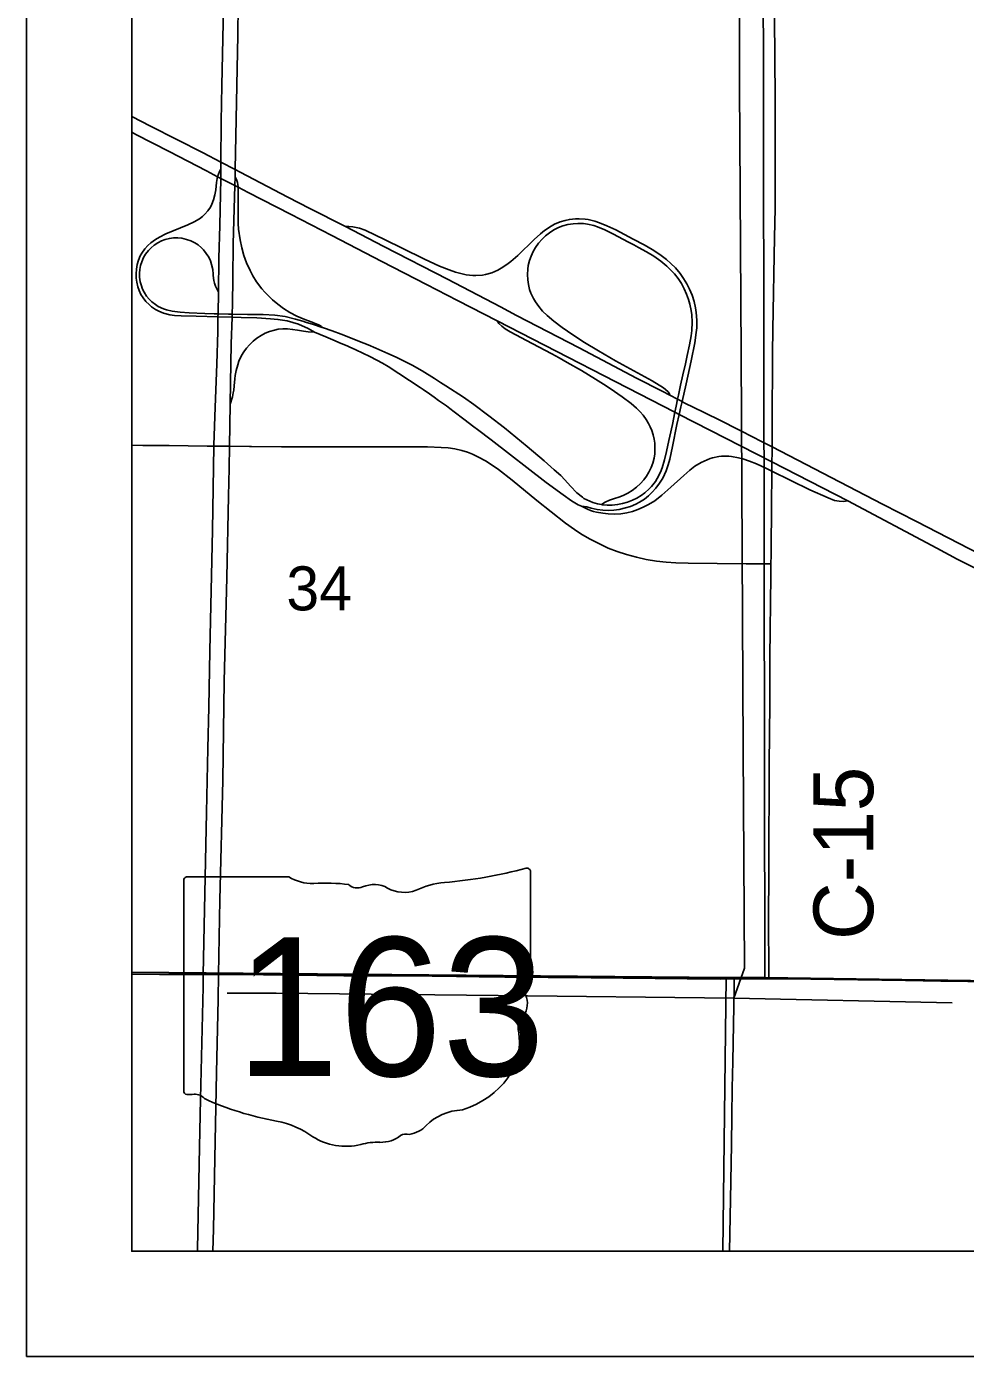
# Model space of a CAD drawing. Extents: x 0 to 34, y 0 to 22.
# Drawn here: x 2 to 2.893, y 14 to 15.265 of the extents above; entities that cross this region are included whole.
import ezdxf

# ---------------------------------------------------------------- set-up
doc = ezdxf.new("R2010")
doc.units = 0
for name, color, linetype in [('Default', 7, 'Continuous'), ('GM_X_County_Road', 7, 'Continuous'), ('GM_X_County_Road_Text', 7, 'Continuous'), ('GM_X_Interchange_Ramps', 7, 'Continuous'), ('GM_X_Interstate_Route', 7, 'Continuous'), ('GM_X_Minor_River', 7, 'Continuous'), ('GM_X_Section', 7, 'Continuous'), ('GM_X_Section_Text', 7, 'Continuous'), ('GM_X_State_Location', 7, 'Continuous'), ('GM_X_State_Route', 7, 'Continuous'), ('GM_X_State_Shield', 7, 'Continuous'), ('GM_X_Township_Road', 7, 'Continuous'), ('SH_Data', 7, 'Continuous')]:
    doc.layers.add(name, color=color, linetype=linetype)

msp = doc.modelspace()

# ---------------------------------------------------------------- linework, layer by layer
at = {"layer": 'Default'}
for points in [[(2.1, 15.3673), (2.1, 14.3654), (2.6651, 14.3602), (2.7019, 14.3602), (2.7001, 15.3638)], [(2.1, 14.3654), (2.1, 14.1), (2.662, 14.1), (2.6651, 14.3602)], [(2.662, 14.1), (3.676, 14.1), (3.6799, 14.3459), (2.7019, 14.3602), (2.6651, 14.3602)]]:
    msp.add_lwpolyline(points, close=True, dxfattribs=at)
at = {"layer": 'GM_X_County_Road'}
for points in [[(2.7076, 14.7538), (2.7078, 14.762), (2.7081, 14.8136), (2.7085, 14.8357), (2.7085, 14.8418), (2.7086, 14.8505), (2.7087, 14.8596), (2.7087, 14.865), (2.7088, 14.8824), (2.7089, 14.9074), (2.7092, 14.9316), (2.7091, 14.954), (2.7095, 14.9764), (2.7111, 15.064), (2.7116, 15.0914), (2.7115, 15.1045), (2.7116, 15.1337), (2.7116, 15.1902), (2.7112, 15.2413), (2.7105, 15.319), (2.7106, 15.3539), (2.7102, 15.3684)], [(2.7055, 14.359), (2.7055, 14.369), (2.7054, 14.4113), (2.7056, 14.4648), (2.7061, 14.563), (2.7065, 14.6208), (2.7067, 14.665), (2.7074, 14.7421), (2.7076, 14.7538)], [(2.6683, 14.1), (2.6692, 14.1493), (2.6702, 14.2016), (2.6705, 14.2283), (2.6709, 14.255), (2.6714, 14.2805), (2.6726, 14.3508), (2.6728, 14.3589)], [(2.6728, 14.3589), (2.6841, 14.359), (2.7055, 14.359)]]:
    msp.add_lwpolyline(points, dxfattribs=at)
at = {"layer": 'GM_X_Interchange_Ramps'}
for points in [[(2.1848, 15.1291), (2.1835, 15.1267), (2.1824, 15.1243), (2.1816, 15.1217), (2.1811, 15.1201), (2.1805, 15.1162), (2.1799, 15.1094), (2.1791, 15.1045), (2.1778, 15.0997), (2.1762, 15.0956), (2.1748, 15.0928), (2.1724, 15.0892), (2.1695, 15.086), (2.1672, 15.0839), (2.1643, 15.0817), (2.1594, 15.0788), (2.1532, 15.076), (2.1325, 15.0674), (2.1263, 15.0644), (2.1225, 15.0622), (2.118, 15.059), (2.1152, 15.0565), (2.1123, 15.0533), (2.1095, 15.0491), (2.1081, 15.0464), (2.1064, 15.0424), (2.1052, 15.0382), (2.1044, 15.0339), (2.1041, 15.0295), (2.1042, 15.0252), (2.1047, 15.0215), (2.1056, 15.0172), (2.1069, 15.0137), (2.1087, 15.0098), (2.1107, 15.0066), (2.1133, 15.0031), (2.1164, 15.0001), (2.1188, 14.9981), (2.1224, 14.9956), (2.1257, 14.9939), (2.1303, 14.992), (2.1363, 14.9905), (2.1406, 14.9899), (2.1468, 14.9894), (2.1611, 14.989), (2.1819, 14.9885), (2.1954, 14.9882), (2.2041, 14.988), (2.219, 14.9875), (2.232, 14.9867), (2.239, 14.9861), (2.2476, 14.9846), (2.2584, 14.9815), (2.2677, 14.9775), (2.2738, 14.9741)], [(2.281, 14.9784), (2.2803, 14.9793), (2.2795, 14.9799), (2.2785, 14.9805), (2.2743, 14.9823), (2.2714, 14.9834), (2.2644, 14.9859), (2.257, 14.989), (2.2504, 14.9926), (2.2441, 14.9965), (2.2387, 15.0007), (2.2339, 15.0047), (2.2264, 15.0121), (2.2235, 15.0153), (2.2187, 15.0218), (2.2151, 15.0276), (2.2124, 15.0325), (2.2091, 15.0398), (2.2066, 15.0468), (2.2046, 15.054), (2.2029, 15.0619), (2.2016, 15.0718), (2.2011, 15.0773), (2.2011, 15.1074), (2.2011, 15.1117), (2.201, 15.1126), (2.2004, 15.1164), (2.1996, 15.1191), (2.1983, 15.1218)], [(2.5275, 14.8085), (2.5326, 14.808), (2.5368, 14.8066), (2.5423, 14.8054), (2.5479, 14.8047), (2.5528, 14.8045), (2.5584, 14.8048), (2.5633, 14.8054), (2.5694, 14.8068), (2.5742, 14.8083), (2.5793, 14.8105), (2.5826, 14.8123), (2.5873, 14.8153), (2.5912, 14.8184), (2.5948, 14.8218), (2.5981, 14.8255), (2.6018, 14.8305), (2.6048, 14.8352), (2.6079, 14.842), (2.6099, 14.8478), (2.6114, 14.8532), (2.614, 14.8653), (2.6183, 14.8861), (2.6204, 14.8958), (2.622, 14.9031), (2.6231, 14.908), (2.6269, 14.9249), (2.6317, 14.9467), (2.6352, 14.9638), (2.6367, 14.9736), (2.6371, 14.978), (2.6373, 14.9854), (2.6367, 14.9928), (2.636, 14.9971), (2.6346, 15.0031), (2.6327, 15.009), (2.6303, 15.0148), (2.6278, 15.0198), (2.6246, 15.0251), (2.6214, 15.0297), (2.617, 15.035), (2.6126, 15.0393), (2.6084, 15.043), (2.602, 15.0479), (2.5946, 15.0526), (2.5871, 15.0569), (2.5767, 15.0625), (2.5684, 15.0668), (2.5601, 15.0711), (2.5517, 15.0752), (2.5448, 15.078), (2.5401, 15.0796), (2.534, 15.081), (2.531, 15.0814), (2.5254, 15.0818), (2.5217, 15.0817), (2.5161, 15.0811), (2.5119, 15.0802), (2.5071, 15.0788), (2.502, 15.0765), (2.4987, 15.0748), (2.4925, 15.0707), (2.4886, 15.0676), (2.4826, 15.0622), (2.467, 15.047), (2.4604, 15.0412), (2.4565, 15.0382), (2.4513, 15.0347), (2.448, 15.033), (2.4424, 15.0305), (2.4364, 15.0289), (2.4333, 15.0283), (2.4272, 15.0279), (2.4241, 15.0279), (2.4179, 15.0286), (2.4142, 15.0293), (2.4076, 15.0311), (2.4017, 15.0331), (2.3925, 15.0368), (2.3783, 15.0433), (2.3572, 15.0537), (2.341, 15.0616), (2.3219, 15.0709), (2.3164, 15.0728), (2.3102, 15.0741), (2.3024, 15.0746)], [(2.6114, 14.9139), (2.6108, 14.9159), (2.6096, 14.9174), (2.6055, 14.9209), (2.5947, 14.9278), (2.5598, 14.9468), (2.5436, 14.9561), (2.5303, 14.9642), (2.5194, 14.9713), (2.5092, 14.9784), (2.5012, 14.9844), (2.495, 14.9897), (2.4906, 14.994), (2.4869, 14.9982), (2.4837, 15.0028), (2.4818, 15.006), (2.4794, 15.0111), (2.4782, 15.0146), (2.477, 15.0194), (2.4764, 15.0237), (2.4761, 15.0287), (2.4764, 15.0337), (2.4769, 15.0374), (2.4781, 15.0422), (2.4796, 15.0463), (2.4817, 15.0508), (2.4839, 15.0546), (2.4867, 15.0587), (2.49, 15.0624), (2.4932, 15.0654), (2.4971, 15.0684), (2.5013, 15.0711), (2.5058, 15.0734), (2.5098, 15.0749), (2.5146, 15.0763), (2.5195, 15.077), (2.5239, 15.0774), (2.5294, 15.0772), (2.5332, 15.0767), (2.5392, 15.0753), (2.5427, 15.0742), (2.5497, 15.0713), (2.558, 15.0672), (2.5717, 15.0598), (2.5773, 15.057), (2.5816, 15.0545), (2.5893, 15.0504), (2.5962, 15.0462), (2.6028, 15.0415), (2.6086, 15.0368), (2.6113, 15.0343), (2.616, 15.0293), (2.6194, 15.0249), (2.6225, 15.0202), (2.6252, 15.0153), (2.6275, 15.0102), (2.6293, 15.0049), (2.6305, 15.0007), (2.6317, 14.9946), (2.6323, 14.9903), (2.6327, 14.9835), (2.6323, 14.9755), (2.6317, 14.9705), (2.6303, 14.9619), (2.628, 14.9516), (2.6263, 14.9437), (2.624, 14.9334), (2.6218, 14.9237), (2.6197, 14.914), (2.6189, 14.9101), (2.6176, 14.9036), (2.6164, 14.8979), (2.6139, 14.886), (2.6116, 14.875), (2.6106, 14.8708), (2.6085, 14.8604), (2.6066, 14.8526), (2.6042, 14.8448), (2.6027, 14.8408), (2.5995, 14.8347), (2.5979, 14.8321), (2.594, 14.8272), (2.5919, 14.825), (2.5877, 14.8213), (2.5842, 14.8187), (2.58, 14.8161), (2.5761, 14.8142), (2.5714, 14.8124), (2.5666, 14.811), (2.5618, 14.81), (2.5568, 14.8095), (2.5518, 14.8095), (2.5475, 14.8099), (2.5466, 14.8101)], [(2.281, 14.9784), (2.2728, 14.9812), (2.2651, 14.9835), (2.2627, 14.9843), (2.2556, 14.9864), (2.2459, 14.9887), (2.236, 14.99), (2.2249, 14.9906), (2.2099, 14.9909), (2.1954, 14.991), (2.1919, 14.991), (2.182, 14.9913), (2.1782, 14.9914), (2.1695, 14.9916), (2.1546, 14.9923), (2.1459, 14.993), (2.1385, 14.9939), (2.1331, 14.9951), (2.1301, 14.9961), (2.1251, 14.9985), (2.1225, 15.0001), (2.119, 15.0028), (2.1164, 15.0054), (2.114, 15.0083), (2.1117, 15.0119), (2.1103, 15.0147), (2.1088, 15.0188), (2.108, 15.0218), (2.1074, 15.0261), (2.1074, 15.0299), (2.1077, 15.0336), (2.1084, 15.0372), (2.1094, 15.0408), (2.1112, 15.0448), (2.1131, 15.048), (2.1158, 15.0515), (2.1183, 15.0542), (2.1212, 15.0566), (2.1248, 15.059), (2.1281, 15.0607), (2.1316, 15.0621), (2.1358, 15.0631), (2.1395, 15.0635), (2.1439, 15.0636), (2.1476, 15.0632), (2.1519, 15.0622), (2.156, 15.0609), (2.1599, 15.0589), (2.163, 15.0569), (2.1664, 15.0541), (2.1681, 15.0523), (2.1708, 15.0489), (2.1731, 15.0452), (2.1747, 15.0419), (2.1758, 15.0383), (2.1769, 15.0334), (2.1774, 15.0291), (2.1775, 15.0279), (2.1781, 15.0231), (2.1786, 15.0205), (2.1796, 15.0176), (2.1823, 15.0119)], [(2.4473, 14.9847), (2.449, 14.9823), (2.4518, 14.9795), (2.4551, 14.9771), (2.4598, 14.9744), (2.4806, 14.9632), (2.4993, 14.9533), (2.5064, 14.9495), (2.514, 14.9452), (2.5274, 14.9374), (2.5407, 14.9293), (2.5486, 14.9244), (2.5548, 14.9203), (2.5661, 14.9126), (2.5746, 14.9062), (2.5797, 14.9018), (2.5832, 14.8982), (2.5861, 14.8949), (2.589, 14.8909), (2.5913, 14.8872), (2.5929, 14.8839), (2.5943, 14.8804), (2.5957, 14.8763), (2.5966, 14.8721), (2.5972, 14.8684), (2.5974, 14.8634), (2.5972, 14.8584), (2.5965, 14.8541), (2.5953, 14.8493), (2.5938, 14.8452), (2.5917, 14.8407), (2.5894, 14.837), (2.5868, 14.8336), (2.5835, 14.8299), (2.5798, 14.8265), (2.5758, 14.8235), (2.5716, 14.8208), (2.5672, 14.8186), (2.5631, 14.8171), (2.5589, 14.8159), (2.554, 14.8142), (2.55, 14.8123), (2.5466, 14.8101)], [(2.1936, 14.9054), (2.1957, 14.9124), (2.1965, 14.9163), (2.197, 14.9188), (2.1972, 14.9228), (2.1979, 14.9296), (2.1984, 14.9327), (2.1993, 14.9376), (2.2007, 14.943), (2.2019, 14.9465), (2.2042, 14.9516), (2.2065, 14.9552), (2.209, 14.9588), (2.2119, 14.962), (2.2155, 14.9654), (2.2189, 14.9682), (2.223, 14.9709), (2.2269, 14.9729), (2.2309, 14.9745), (2.2356, 14.976), (2.2393, 14.9767), (2.2436, 14.9772), (2.2479, 14.9771), (2.2529, 14.9765), (2.2576, 14.9757), (2.2631, 14.975), (2.2678, 14.9744), (2.2738, 14.9741)], [(2.2738, 14.9741), (2.2845, 14.9695), (2.2911, 14.9667), (2.2992, 14.9633), (2.3049, 14.9608), (2.3066, 14.96), (2.3129, 14.9573), (2.3196, 14.9541), (2.3263, 14.9508), (2.3329, 14.9474), (2.3383, 14.9445), (2.3436, 14.9413), (2.3742, 14.9213), (2.3769, 14.9195), (2.3829, 14.9153), (2.3876, 14.912), (2.3917, 14.9091), (2.3991, 14.9038), (2.4023, 14.9014), (2.4064, 14.8983), (2.4157, 14.8913), (2.4253, 14.8838), (2.4288, 14.8813), (2.4416, 14.8716), (2.494, 14.831), (2.51, 14.8192), (2.5181, 14.8137), (2.5245, 14.8099), (2.5275, 14.8085)], [(2.5466, 14.8101), (2.5426, 14.8108), (2.5384, 14.812), (2.5355, 14.8131), (2.5299, 14.8158), (2.5284, 14.8169), (2.5232, 14.8213), (2.5172, 14.8276), (2.5118, 14.8336), (2.5079, 14.8376), (2.5016, 14.8431), (2.492, 14.8516), (2.4758, 14.8652), (2.4543, 14.883), (2.4395, 14.8944), (2.4251, 14.9053), (2.4154, 14.912), (2.3987, 14.9228), (2.3935, 14.9262), (2.3878, 14.9299), (2.3761, 14.9371), (2.3664, 14.9426), (2.3558, 14.9479), (2.3514, 14.9501), (2.3434, 14.9537), (2.3321, 14.9588), (2.3247, 14.962), (2.3166, 14.9652), (2.3032, 14.9703), (2.2992, 14.9719), (2.2904, 14.9751), (2.2822, 14.978), (2.281, 14.9784)], [(2.5275, 14.8085), (2.5294, 14.8075), (2.5331, 14.8056), (2.5362, 14.8043), (2.5388, 14.8035), (2.5417, 14.8029), (2.5479, 14.8018), (2.5529, 14.8012), (2.5593, 14.8008), (2.5649, 14.8013), (2.5705, 14.8022), (2.5759, 14.8035), (2.5812, 14.8053), (2.5863, 14.8075), (2.5913, 14.8101), (2.5971, 14.8137), (2.604, 14.819), (2.6124, 14.8264), (2.6248, 14.8378), (2.6305, 14.8426), (2.6354, 14.8464), (2.6413, 14.85), (2.644, 14.8514), (2.6498, 14.8537), (2.6521, 14.8544), (2.6582, 14.8556), (2.6607, 14.8559), (2.6675, 14.8559), (2.67, 14.8557), (2.6767, 14.8545), (2.6809, 14.8534), (2.6874, 14.8513), (2.6938, 14.8487), (2.704, 14.8441), (2.7085, 14.8418), (2.7447, 14.8241), (2.7621, 14.8164), (2.7682, 14.8139), (2.7724, 14.8132), (2.7763, 14.8129), (2.7808, 14.8135)]]:
    msp.add_lwpolyline(points, dxfattribs=at)
at = {"layer": 'GM_X_Interstate_Route'}
for points in [[(2.1, 20.9), (2.1, 14.3639), (2.1262, 14.3636), (2.1461, 14.3637), (2.161, 14.3637), (2.1678, 14.3636), (2.179, 14.3636), (2.1822, 14.3636), (2.1952, 14.3635), (2.225, 14.3635), (2.2499, 14.3631), (2.3015, 14.3626), (2.3854, 14.362), (2.4084, 14.3617), (2.4301, 14.3614), (2.4544, 14.3611), (2.5365, 14.3604), (2.6279, 14.3594), (2.6596, 14.3593), (2.6725, 14.3594), (2.6838, 14.3596), (2.7053, 14.3596), (2.723, 14.3595), (2.7901, 14.3585), (2.8355, 14.3579), (2.8691, 14.3573), (2.8946, 14.3569)], [(2.1848, 15.1291), (2.1848, 15.1356), (2.1851, 15.1744), (2.1857, 15.2086), (2.1874, 15.2981)], [(2.1983, 15.1218), (2.1984, 15.1285), (2.2007, 15.2563), (2.2012, 15.285)], [(2.1, 15.179), (2.1179, 15.1697), (2.1677, 15.1444), (2.1848, 15.1356), (2.1984, 15.1285), (2.2031, 15.1261), (2.2482, 15.1024), (2.2692, 15.0916), (2.3024, 15.0746), (2.3395, 15.0555), (2.4002, 15.0242), (2.4504, 14.9981), (2.4658, 14.9899), (2.5253, 14.9589), (2.5583, 14.9416), (2.5798, 14.9303), (2.6041, 14.9177), (2.6114, 14.9139), (2.6189, 14.9101), (2.6231, 14.908), (2.6251, 14.9069), (2.644, 14.8974), (2.6602, 14.8896), (2.6757, 14.8817), (2.6934, 14.8727), (2.6956, 14.8715), (2.7051, 14.8669), (2.7087, 14.865), (2.757, 14.8399), (2.8138, 14.8105), (2.8459, 14.794), (2.9769, 14.7265)], [(2.1, 15.1641), (2.104, 15.162), (2.1354, 15.1456), (2.171, 15.1273)], [(2.171, 15.1273), (2.1816, 15.1217), (2.1846, 15.1202), (2.198, 15.1133), (2.2011, 15.1117), (2.2105, 15.1068), (2.2509, 15.0861), (2.2902, 15.0659), (2.3376, 15.0412), (2.3802, 15.0192)], [(2.3802, 15.0192), (2.4095, 15.0041), (2.4473, 14.9847)], [(2.4473, 14.9847), (2.6164, 14.8979), (2.6204, 14.8958), (2.7086, 14.8505), (2.7808, 14.8135)], [(2.7808, 14.8135), (2.8655, 14.7685), (2.8848, 14.7582), (2.9264, 14.7371), (3.0022, 14.6983), (3.1397, 14.6271), (3.2203, 14.5854), (3.3213, 14.533), (3.3689, 14.5086), (3.4054, 14.4898), (3.4722, 14.4553), (3.533, 14.4239), (3.5854, 14.3967), (3.6138, 14.3818)], [(2.8946, 14.3569), (2.8691, 14.3573), (2.8355, 14.3579), (2.7901, 14.3585), (2.723, 14.3595), (2.7053, 14.3596), (2.6838, 14.3596), (2.6725, 14.3594), (2.6596, 14.3593), (2.6279, 14.3594), (2.5365, 14.3604), (2.4544, 14.3611), (2.4301, 14.3614), (2.4084, 14.3617), (2.3854, 14.362), (2.3015, 14.3626), (2.2499, 14.3631), (2.225, 14.3635), (2.1952, 14.3635), (2.1822, 14.3636), (2.179, 14.3636), (2.1678, 14.3636), (2.161, 14.3637), (2.1461, 14.3637), (2.1262, 14.3636), (2.1, 14.3639), (2.1, 14.1), (4.7021, 14.1)]]:
    msp.add_lwpolyline(points, dxfattribs=at)
at = {"layer": 'GM_X_Minor_River'}
for points in [[(2.6723, 14.3408), (2.6826, 14.3691), (2.6813, 14.5774), (2.6793, 14.9534), (2.6777, 15.2084), (2.6779, 15.3894), (2.6785, 15.7411), (2.6841, 15.9829)], [(2.8799, 14.3363), (2.6723, 14.3408), (2.4484, 14.3432), (2.2373, 14.3455), (2.1908, 14.3455)]]:
    msp.add_lwpolyline(points, dxfattribs=at)
at = {"layer": 'GM_X_Section'}
msp.add_lwpolyline([(3.7036, 15.3519), (3.7061, 14.3445), (3.6799, 14.3459), (2.7019, 14.3602), (2.7001, 15.3638)], close=True, dxfattribs=at)
at = {"layer": 'GM_X_State_Route'}
for points in [[(2.168, 14.3631), (2.171, 14.5172), (2.1724, 14.5782), (2.1732, 14.6173), (2.1743, 14.6708), (2.1767, 14.7858), (2.178, 14.8655), (2.178, 14.8666), (2.1794, 14.9026), (2.181, 14.9436), (2.1817, 14.9747), (2.1819, 14.9885), (2.182, 14.9913), (2.1823, 15.0119), (2.1828, 15.0443), (2.1836, 15.0754), (2.1846, 15.1202), (2.1848, 15.1291)], [(2.1824, 14.363), (2.1838, 14.4343), (2.1864, 14.5475), (2.1879, 14.642), (2.1903, 14.7408), (2.1919, 14.8179), (2.1926, 14.8446), (2.1929, 14.8654), (2.1936, 14.9054), (2.1939, 14.9254), (2.1946, 14.9628), (2.1954, 14.9882), (2.1954, 14.991), (2.1957, 15.0007), (2.1962, 15.0249), (2.1964, 15.0579), (2.198, 15.1133), (2.1983, 15.1218)], [(2.1, 14.3634), (2.1264, 14.363), (2.1463, 14.3631), (2.1612, 14.3632), (2.168, 14.3631), (2.1793, 14.363), (2.1824, 14.363)], [(2.1625, 14.1), (2.1625, 14.102), (2.1643, 14.199), (2.1653, 14.245), (2.1678, 14.3513), (2.168, 14.3631)], [(2.1772, 14.1), (2.1776, 14.121), (2.1791, 14.1881), (2.1804, 14.2696), (2.182, 14.3398), (2.1824, 14.363)], [(2.1824, 14.363), (2.1954, 14.363), (2.2253, 14.3629), (2.2432, 14.3627)], [(2.2432, 14.3627), (2.2501, 14.3626), (2.3017, 14.362), (2.3856, 14.3615), (2.4086, 14.3612), (2.4304, 14.3609), (2.4546, 14.3605), (2.5367, 14.3599), (2.6281, 14.3589), (2.6598, 14.3587), (2.6728, 14.3589)], [(2.6728, 14.3589), (2.6841, 14.359), (2.7055, 14.359)], [(2.7055, 14.359), (2.7232, 14.359), (2.7903, 14.358), (2.8357, 14.3574), (2.8693, 14.3567), (2.8948, 14.3564), (2.9563, 14.3554), (2.9955, 14.355), (3.0589, 14.3544), (3.0888, 14.354), (3.108, 14.3538), (3.136, 14.3533), (3.1913, 14.3525), (3.2355, 14.3521), (3.2548, 14.3517), (3.2893, 14.3516), (3.2933, 14.3516), (3.3188, 14.3516), (3.3648, 14.3511), (3.4002, 14.3504), (3.4513, 14.3505)]]:
    msp.add_lwpolyline(points, dxfattribs=at)
at = {"layer": 'GM_X_State_Shield'}
for p, q in [((2.2492, 14.456), (2.1527, 14.456)), ((2.479, 14.3563), (2.479, 14.461)), ((2.1494, 14.4526), (2.1494, 14.2524)), ((2.479, 14.3563), (2.479, 14.3563))]:
    msp.add_line(p, q, dxfattribs=at)
for centre, major_axis, start_param, end_param in [((2.1532, 14.453), (0.00382, 0), 1.712693, 3.28349), ((2.2722, 14.4792), (0.037, 0), 4.042523, 4.731795), ((2.3616, 14.7288), (0.3495, 0), 4.814394, 5.042369), ((2.4753, 14.4614), (0.00367, 0), 6.141152, 7.989035), ((2.2844, 14.3437), (0.133, 0), 1.404758, 1.657858), ((2.3146, 14.454), (0.0107, 0), 3.836095, 5.185415), ((2.3303, 14.4309), (0.0222, 0), 0.950623, 2.079405), ((2.359, 14.4626), (0.0267, 0), 4.081561, 5.145723), ((2.4062, 14.3949), (0.0703, 0), 1.699011, 2.107814), ((2.4781, 14.3486), (0.00568, 0), 1.883978, 3.671073), ((2.4751, 14.3559), (0.00393, 0), 5.05454, 6.418171), ((2.442, 14.3354), (0.0341, 0), 5.934695, 6.695948), ((2.4921, 14.3125), (0.0248, 0), 2.387724, 3.262537), ((2.3812, 14.2991), (0.0874, 0), 5.101752, 6.440018), ((2.1532, 14.252), (0.00385, 0), 3.00124, 4.508301), ((2.1538, 14.2725), (0.0294, 0), 4.665946, 4.897461), ((2.1598, 14.2409), (0.0106, 0), 0.519207, 1.627899), ((2.2936, 14.4207), (0.2524, 0), 4.195997, 4.488961), ((2.418, 14.1963), (0.0479, 0), 1.647645, 2.488434), ((2.2184, 14.1625), (0.079, 0), 0.823519, 1.323587), ((2.3574, 14.233), (0.0282, 0), 4.937069, 5.64225), ((2.3038, 14.2399), (0.0501, 0), 4.026481, 4.996735), ((2.3328, 14.1707), (0.0412, 0), 1.495662, 1.94098), ((2.3364, 14.2249), (0.0267, 0), 4.691044, 5.507374), ((2.3606, 14.2055), (0.00752, 0), 1.147584, 2.315152)]:
    msp.add_ellipse(centre, major_axis=major_axis, ratio=0.8, start_param=start_param, end_param=end_param, dxfattribs=at)
at = {"layer": 'GM_X_Township_Road'}
for points in [[(2.1, 14.8664), (2.1106, 14.8662), (2.1236, 14.8661)], [(2.1236, 14.8661), (2.1355, 14.8661), (2.1716, 14.8656), (2.178, 14.8655)], [(2.178, 14.8655), (2.1858, 14.8655), (2.1929, 14.8654), (2.2119, 14.8651), (2.2139, 14.8651)], [(2.2139, 14.8651), (2.2423, 14.8649), (2.284, 14.865), (2.3362, 14.8648), (2.3623, 14.8649), (2.381, 14.8649), (2.3941, 14.8644), (2.4009, 14.8639), (2.4071, 14.8629), (2.4139, 14.8613), (2.4193, 14.8597), (2.424, 14.8579), (2.4297, 14.8552), (2.4363, 14.8516), (2.4426, 14.8476), (2.4487, 14.8432), (2.4615, 14.8332), (2.485, 14.8139), (2.4986, 14.803), (2.5123, 14.7923), (2.5208, 14.7862), (2.527, 14.7821), (2.5351, 14.7775), (2.5439, 14.7729), (2.5528, 14.7687), (2.5615, 14.7654), (2.5703, 14.7625), (2.5798, 14.7599), (2.5889, 14.7579), (2.5987, 14.7563), (2.6079, 14.7552), (2.6171, 14.7546), (2.6289, 14.7544), (2.6842, 14.7537), (2.7016, 14.7538), (2.7076, 14.7538)]]:
    msp.add_lwpolyline(points, dxfattribs=at)
at = {"layer": 'SH_Data'}
for p, q in [((2, 21), (2, 14)), ((2.1, 20.9), (2.1, 14.1)), ((2.1, 14.1), (8.9, 14.1)), ((2.1, 14.1), (2.1, 14.1)), ((2, 14), (9, 14))]:
    msp.add_line(p, q, dxfattribs=at)

# ---------------------------------------------------------------- texts
at = {"layer": 'GM_X_County_Road_Text'}
msp.add_text('C-15', height=0.05682, rotation=90, dxfattribs=at).set_placement((2.8049, 14.396))
at = {"layer": 'GM_X_Section_Text'}
msp.add_text('34', height=0.04186, rotation=0, dxfattribs=at).set_placement((2.247, 14.7094))
at = {"layer": 'GM_X_State_Location'}
for s in ['s', 'r']:
    msp.add_text(s, height=0.000189, dxfattribs=at).set_placement((2.3105, 14.3392))
msp.add_text('163', height=0.000189, rotation=0, dxfattribs=at).set_placement((2.2436, 14.3254))
at = {"layer": 'GM_X_State_Shield'}
msp.add_text('163', height=0.13184, dxfattribs=at).set_placement((2.1989, 14.2666))

doc.saveas('drawing.dxf')
